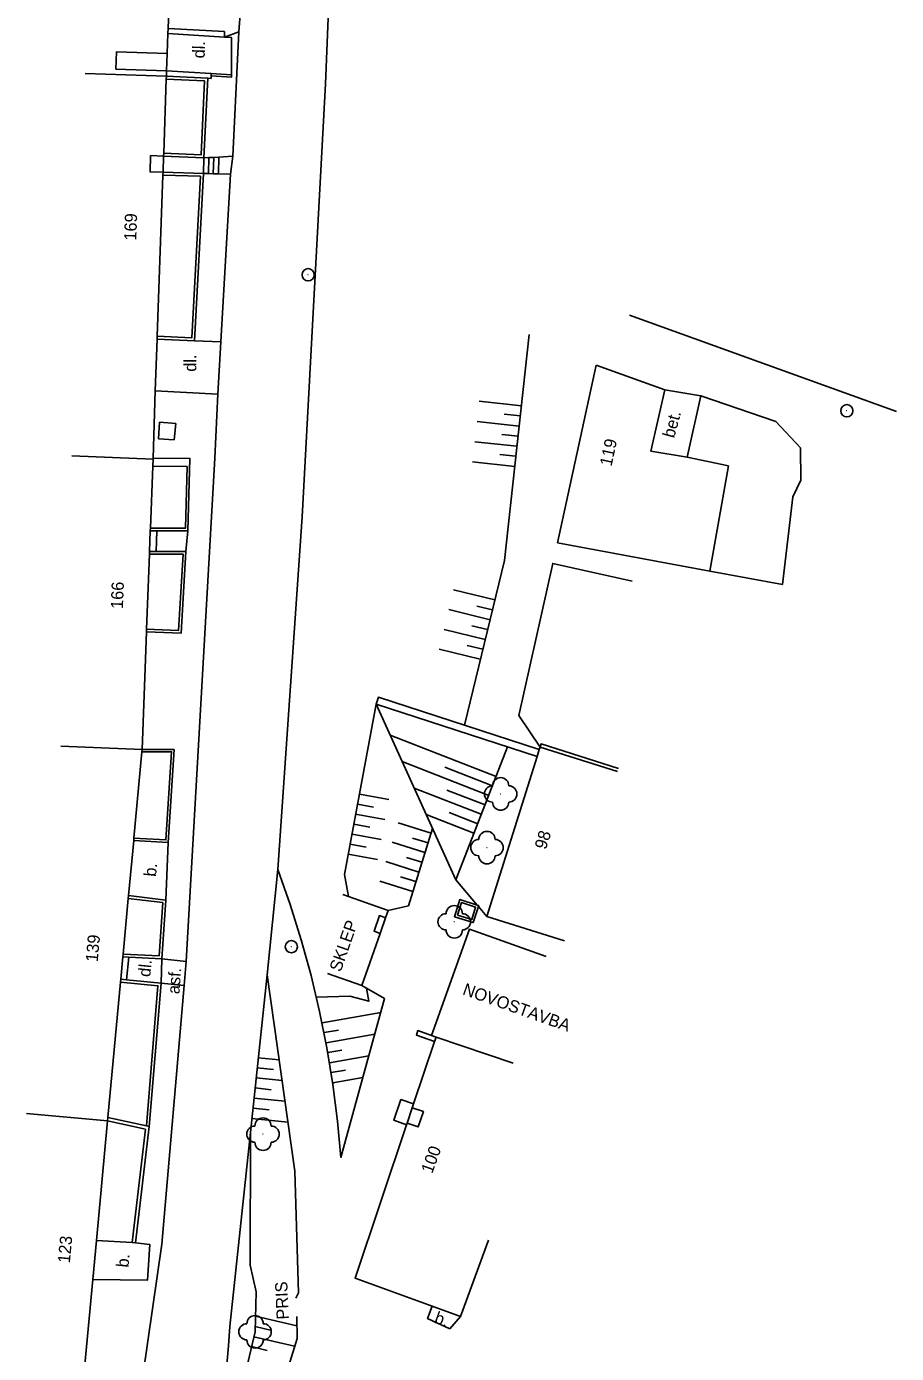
# Model space of a CAD drawing. Extents: x -582162 to -561283, y -1187583 to -1183539.
# Drawn here: x -571349.5 to -571296.1, y -1184989.4 to -1184907.8 of the extents above; entities that cross this region are included whole.
import ezdxf

# ---------------------------------------------------------------- set-up
doc = ezdxf.new("R2010")
doc.units = 0
for name, color, linetype in [('Vrstva 1', 7, 'Continuous'), ('Vrstva 10', 7, 'Continuous'), ('Vrstva 11', 7, 'Continuous'), ('Vrstva 12', 7, 'Continuous'), ('Vrstva 14', 7, 'Continuous'), ('Vrstva 4', 7, 'Continuous'), ('Vrstva 5', 7, 'Continuous'), ('Vrstva 6', 7, 'Continuous'), ('Vrstva 9', 7, 'Continuous')]:
    doc.layers.add(name, color=color, linetype=linetype)

# ---------------------------------------------------------------- blocks, each defined once
blk = doc.blocks.new('1.079')
at = {"layer": 'Vrstva 1'}
for radius in [0.75, 0.001]:
    blk.add_circle((0, -0.001), radius, dxfattribs=at)
blk = doc.blocks.new('3.130')
at = {"layer": 'Vrstva 1'}
blk.add_circle((0, 0), 0.001, dxfattribs=at)
for centre, start, end in [((0, 1), 0, 180), ((-1, 0), 90, 270), ((1, 0), 270, 90), ((0, -1), 180, 360)]:
    blk.add_arc(centre, 1, start, end, dxfattribs=at)

msp = doc.modelspace()

# ---------------------------------------------------------------- linework, layer by layer
at = {"layer": 'Vrstva 10'}
for points in [[(-571332.31, -1184869.17), (-571335.96, -1184901.1), (-571336.48, -1184908.14)], [(-571334.08, -1184959.63), (-571332.59, -1184937.95), (-571331.16, -1184911.33), (-571330.53, -1184895.66), (-571330.24, -1184892.9)], [(-571336.48, -1184908.14), (-571337.37, -1184908.46)], [(-571337.37, -1184908.46), (-571336.94, -1184908.48), (-571336.93, -1184910.78)], [(-571336.48, -1184908.14), (-571336.86, -1184915.79)], [(-571337.71, -1184915.84), (-571338.03, -1184915.86)], [(-571337.73, -1184916.87), (-571337.71, -1184915.84)], [(-571336.86, -1184915.79), (-571337.71, -1184915.84)], [(-571336.86, -1184915.79), (-571337, -1184916.88)], [(-571338.63, -1184915.89), (-571338.66, -1184916.85)], [(-571338.33, -1184915.87), (-571338.63, -1184915.89)], [(-571338.36, -1184916.85), (-571338.33, -1184915.87)], [(-571338.03, -1184915.86), (-571338.33, -1184915.87)], [(-571338.06, -1184916.86), (-571338.03, -1184915.86)], [(-571338.66, -1184916.85), (-571338.36, -1184916.85)], [(-571338.36, -1184916.85), (-571338.06, -1184916.86)], [(-571338.06, -1184916.86), (-571337.73, -1184916.87)], [(-571337.73, -1184916.87), (-571337, -1184916.88)], [(-571337, -1184916.88), (-571337.6, -1184927.19)], [(-571337.6, -1184927.19), (-571339.21, -1184927.14)], [(-571337.6, -1184927.19), (-571337.77, -1184930.41)], [(-571337.77, -1184930.41), (-571341.62, -1184930.21)], [(-571337.77, -1184930.41), (-571337.97, -1184934.35), (-571339.73, -1184965.27)], [(-571308.09, -1184930.51), (-571310.32, -1184930.14)], [(-571308.94, -1184934.29), (-571308.09, -1184930.51)], [(-571341.42, -1184933.16), (-571341.36, -1184932.14)], [(-571341.36, -1184932.14), (-571340.35, -1184932.21)], [(-571340.35, -1184932.21), (-571340.45, -1184933.22)], [(-571340.45, -1184933.22), (-571341.42, -1184933.16)], [(-571341.52, -1184938.8), (-571341.57, -1184940.08)], [(-571339.61, -1184938.82), (-571339.74, -1184940.09)], [(-571318.03, -1184952.25), (-571327.91, -1184949.04), (-571328.05, -1184949.47)], [(-571318.16, -1184952.68), (-571328.05, -1184949.47)], [(-571328.05, -1184949.47), (-571323.16, -1184960.25), (-571321.84, -1184961.81)], [(-571313.15, -1184953.41), (-571317.92, -1184951.91), (-571317.98, -1184952.1)], [(-571340.83, -1184957.97), (-571340.97, -1184961.5)], [(-571334.75, -1184966.09), (-571334.08, -1184959.63)], [(-571334.08, -1184959.63), (-571333.33, -1184961.78), (-571332.65, -1184963.95), (-571332.04, -1184966.14), (-571331.52, -1184968.36), (-571331.07, -1184970.59), (-571330.71, -1184972.84), (-571330.42, -1184975.09), (-571330.21, -1184977.32), (-571327.53, -1184967.56), (-571328.92, -1184966.75)], [(-571321.77, -1184961.9), (-571322.08, -1184962.89), (-571323.23, -1184962.53), (-571322.91, -1184961.47), (-571321.84, -1184961.81)], [(-571323.05, -1184962.43), (-571322.81, -1184961.66), (-571321.94, -1184961.94), (-571322.18, -1184962.7), (-571323.05, -1184962.43)], [(-571321.84, -1184961.81), (-571321.75, -1184961.84), (-571321.77, -1184961.9)], [(-571321.84, -1184961.81), (-571321.77, -1184961.9)], [(-571321.77, -1184961.9), (-571321.25, -1184962.51)], [(-571343.25, -1184965.02), (-571343.38, -1184966.4)], [(-571341.21, -1184965.12), (-571341.26, -1184966.61)], [(-571339.73, -1184965.27), (-571341.21, -1184965.12)], [(-571339.73, -1184965.27), (-571339.84, -1184966.76)], [(-571338.89, -1185000), (-571338.44, -1184998.07), (-571337.99, -1184995.8), (-571337.62, -1184993.52), (-571337.33, -1184991.22), (-571337.12, -1184988.91), (-571337.04, -1184987.72), (-571335.77, -1184975.78), (-571334.75, -1184966.09)], [(-571332.82, -1184985.64), (-571333.05, -1184978.17), (-571334.75, -1184966.09)], [(-571339.84, -1184966.76), (-571341.22, -1184982.66), (-571342.67, -1184992.73), (-571342.71, -1184993.13), (-571342.94, -1184995.04), (-571343.25, -1184996.93), (-571343.64, -1184998.81), (-571343.94, -1185000)], [(-571341.26, -1184966.61), (-571339.84, -1184966.76)], [(-571326.18, -1184975.31), (-571326.97, -1184975.04), (-571326.53, -1184973.77), (-571325.75, -1184974.03)], [(-571342.83, -1184982.58), (-571341.96, -1184982.67), (-571342.09, -1184984.86), (-571345.46, -1184984.82)], [(-571345.24, -1184982.43), (-571343.05, -1184982.56)], [(-571322.86, -1184987.1), (-571323.53, -1184987.85), (-571324.89, -1184987.23), (-571324.61, -1184986.46)], [(-571334.01, -1184992.04), (-571332.91, -1184988.45), (-571332.93, -1184987.1)]]:
    msp.add_lwpolyline(points, dxfattribs=at)
at = {"layer": 'Vrstva 12'}
for points in [[(-571321.71, -1184930.84), (-571319.12, -1184931.13)], [(-571321.85, -1184932.08), (-571319.26, -1184932.37)], [(-571320.18, -1184931.64), (-571319.19, -1184931.75)], [(-571320.32, -1184932.88), (-571319.33, -1184932.99)], [(-571321.99, -1184933.33), (-571319.4, -1184933.61)], [(-571322.12, -1184934.57), (-571319.53, -1184934.85)], [(-571320.45, -1184934.12), (-571319.46, -1184934.23)], [(-571323.29, -1184942.44), (-571320.76, -1184943.05)], [(-571321.87, -1184943.43), (-571320.91, -1184943.66)], [(-571323.58, -1184943.65), (-571321.05, -1184944.27)], [(-571323.88, -1184944.87), (-571321.35, -1184945.48)], [(-571322.17, -1184944.64), (-571321.2, -1184944.88)], [(-571322.46, -1184945.86), (-571321.5, -1184946.09)], [(-571324.18, -1184946.08), (-571321.65, -1184946.7)], [(-571327.19, -1184951.36), (-571320.68, -1184953.9)], [(-571326.45, -1184952.99), (-571321.13, -1184955.07)], [(-571323.83, -1184953.34), (-571320.91, -1184954.48)], [(-571327.28, -1184955.33), (-571329.08, -1184955)], [(-571325.71, -1184954.62), (-571321.59, -1184956.23)], [(-571323.7, -1184954.74), (-571321.36, -1184955.65)], [(-571328.21, -1184955.8), (-571329.19, -1184955.61)], [(-571327.51, -1184956.56), (-571329.31, -1184956.23)], [(-571324.97, -1184956.25), (-571322.04, -1184957.39)], [(-571323.56, -1184956.13), (-571321.81, -1184956.81)], [(-571328.44, -1184957.02), (-571329.42, -1184956.84)], [(-571326.7, -1184956.76), (-571324.67, -1184957.39)], [(-571328.67, -1184958.25), (-571329.65, -1184958.07)], [(-571327.74, -1184957.79), (-571329.53, -1184957.46)], [(-571327.07, -1184957.95), (-571325.05, -1184958.59)], [(-571325.81, -1184957.69), (-571324.86, -1184957.99)], [(-571327.97, -1184959.02), (-571329.76, -1184958.69)], [(-571326.18, -1184958.88), (-571325.24, -1184959.18)], [(-571327.45, -1184959.14), (-571325.42, -1184959.78)], [(-571327.82, -1184960.34), (-571325.8, -1184960.97)], [(-571326.56, -1184960.08), (-571325.61, -1184960.37)], [(-571327.76, -1184968.42), (-571331.37, -1184969.04)], [(-571330.36, -1184969.5), (-571331.25, -1184969.65)], [(-571328.13, -1184969.75), (-571331.13, -1184970.27)], [(-571334.01, -1184971.32), (-571335.29, -1184971.19)], [(-571330.15, -1184970.73), (-571331.02, -1184970.88)], [(-571328.5, -1184971.08), (-571330.91, -1184971.5)], [(-571334.36, -1184971.91), (-571335.35, -1184971.81)], [(-571329.94, -1184971.96), (-571330.81, -1184972.11)], [(-571333.83, -1184972.6), (-571335.42, -1184972.43)], [(-571328.86, -1184972.41), (-571330.72, -1184972.73)], [(-571333.65, -1184973.87), (-571335.55, -1184973.67)], [(-571334.49, -1184973.16), (-571335.48, -1184973.05)], [(-571334.62, -1184974.4), (-571335.61, -1184974.3)], [(-571333.47, -1184975.15), (-571335.68, -1184974.92)], [(-571332.93, -1184987.68), (-571335.46, -1184987.08)], [(-571333.06, -1184988.93), (-571335.56, -1184988.34)], [(-571334.45, -1184987.96), (-571335.48, -1184987.72)], [(-571334.74, -1184989.18), (-571335.71, -1184988.95)]]:
    msp.add_lwpolyline(points, dxfattribs=at)
at = {"layer": 'Vrstva 4'}
for points in [[(-571340.61, -1184901.83), (-571340.83, -1184907.93)], [(-571340.84, -1184908.24), (-571340.89, -1184909.47)], [(-571340.83, -1184907.93), (-571340.84, -1184908.24)], [(-571340.93, -1184910.54), (-571344.04, -1184910.43), (-571344, -1184909.36), (-571340.89, -1184909.47)], [(-571340.89, -1184909.47), (-571340.93, -1184910.54)], [(-571345.93, -1184910.7), (-571340.94, -1184910.87)], [(-571340.94, -1184910.87), (-571340.95, -1184911.05)], [(-571340.93, -1184910.54), (-571340.94, -1184910.87)], [(-571340.95, -1184911.05), (-571341.1, -1184915.6)], [(-571341.11, -1184915.78), (-571341.91, -1184915.75), (-571341.94, -1184916.75), (-571341.14, -1184916.77)], [(-571341.11, -1184915.78), (-571341.14, -1184916.77)], [(-571341.1, -1184915.6), (-571341.11, -1184915.78)], [(-571341.15, -1184916.95), (-571341.5, -1184926.85)], [(-571341.14, -1184916.77), (-571341.15, -1184916.95)], [(-571341.51, -1184927.03), (-571341.62, -1184930.21)], [(-571341.5, -1184926.85), (-571341.51, -1184927.03)], [(-571316.9, -1184939.55), (-571314.53, -1184928.63)], [(-571314.53, -1184928.63), (-571310.32, -1184930.14)], [(-571341.62, -1184930.21), (-571341.76, -1184934.34)], [(-571311.17, -1184933.92), (-571310.32, -1184930.14)], [(-571346.75, -1184934.21), (-571341.76, -1184934.4)], [(-571341.76, -1184934.4), (-571341.78, -1184934.84)], [(-571341.76, -1184934.34), (-571341.76, -1184934.4)], [(-571311.17, -1184933.92), (-571308.94, -1184934.29)], [(-571306.4, -1184934.82), (-571308.94, -1184934.29)], [(-571341.78, -1184934.84), (-571341.92, -1184938.64)], [(-571307.55, -1184941.29), (-571306.4, -1184934.82)], [(-571341.92, -1184938.64), (-571341.93, -1184938.8)], [(-571341.93, -1184938.8), (-571341.97, -1184940.08)], [(-571341.98, -1184940.24), (-571342.15, -1184944.85)], [(-571341.97, -1184940.08), (-571341.98, -1184940.24)], [(-571342.16, -1184945.01), (-571342.43, -1184952.24)], [(-571342.15, -1184944.85), (-571342.16, -1184945.01)], [(-571347.43, -1184952.05), (-571342.43, -1184952.24)], [(-571342.44, -1184952.39), (-571342.93, -1184957.69)], [(-571342.43, -1184952.24), (-571342.44, -1184952.39)], [(-571318.16, -1184952.68), (-571318.03, -1184952.25)], [(-571318.03, -1184952.25), (-571317.98, -1184952.1)], [(-571317.98, -1184952.1), (-571313.21, -1184953.6)], [(-571321.25, -1184962.51), (-571318.16, -1184952.68)], [(-571342.94, -1184957.84), (-571343.26, -1184961.23)], [(-571342.93, -1184957.69), (-571342.94, -1184957.84)], [(-571343.28, -1184961.41), (-571343.59, -1184964.82)], [(-571343.26, -1184961.23), (-571343.28, -1184961.41)], [(-571330.1, -1184961.16), (-571327.31, -1184962.14), (-571327.47, -1184962.59)], [(-571327.47, -1184962.59), (-571327.84, -1184962.46), (-571328.18, -1184963.42), (-571327.8, -1184963.55)], [(-571327.47, -1184962.59), (-571327.8, -1184963.55)], [(-571316.48, -1184964.01), (-571321.25, -1184962.51)], [(-571327.8, -1184963.55), (-571328.92, -1184966.75)], [(-571324.64, -1184969.83), (-571322.32, -1184963.3), (-571317.6, -1184964.97)], [(-571343.61, -1184965), (-571343.74, -1184966.37)], [(-571343.59, -1184964.82), (-571343.61, -1184965)], [(-571343.74, -1184966.37), (-571343.76, -1184966.55)], [(-571328.92, -1184966.75), (-571331.04, -1184966.01)], [(-571343.76, -1184966.55), (-571344.53, -1184974.86)], [(-571325.75, -1184974.03), (-571324.46, -1184970.19)], [(-571324.37, -1184969.93), (-571324.64, -1184969.83)], [(-571324.46, -1184970.19), (-571324.37, -1184969.93)], [(-571319.63, -1184971.52), (-571324.37, -1184969.93)], [(-571326.15, -1184975.22), (-571325.83, -1184974.27)], [(-571326.15, -1184975.22), (-571325.46, -1184975.45), (-571325.14, -1184974.5), (-571325.83, -1184974.27)], [(-571325.83, -1184974.27), (-571325.75, -1184974.03)], [(-571349.53, -1184974.62), (-571344.55, -1184975.08)], [(-571344.55, -1184975.08), (-571345.24, -1184982.43)], [(-571344.53, -1184974.86), (-571344.55, -1184975.08)], [(-571324.61, -1184986.46), (-571329.34, -1184984.74), (-571326.18, -1184975.31)], [(-571326.18, -1184975.31), (-571326.15, -1184975.22)], [(-571345.24, -1184982.43), (-571345.46, -1184984.82)], [(-571321.14, -1184982.4), (-571322.86, -1184987.1)], [(-571345.46, -1184984.82), (-571346.13, -1184992.02)], [(-571322.86, -1184987.1), (-571324.61, -1184986.46)]]:
    msp.add_lwpolyline(points, dxfattribs=at)
at = {"layer": 'Vrstva 5'}
msp.add_lwpolyline([(-571316.9, -1184939.55), (-571307.55, -1184941.29)], dxfattribs=at)
at = {"layer": 'Vrstva 9'}
for points in [[(-571337.37, -1184908.46), (-571340.84, -1184908.24)], [(-571340.83, -1184907.93), (-571337.37, -1184908.13), (-571337.37, -1184908.46)], [(-571338.4, -1184910.99), (-571340.94, -1184910.87)], [(-571338.18, -1184910.7), (-571340.93, -1184910.54)], [(-571338.19, -1184910.85), (-571338.19, -1184911), (-571338.4, -1184910.99)], [(-571338.18, -1184910.7), (-571338.19, -1184910.85)], [(-571336.93, -1184910.78), (-571336.94, -1184910.93), (-571338.19, -1184910.85)], [(-571338.18, -1184910.7), (-571336.93, -1184910.78)], [(-571341.1, -1184915.6), (-571338.8, -1184915.7), (-571338.59, -1184911.16), (-571340.95, -1184911.05)], [(-571338.63, -1184915.89), (-571338.4, -1184910.99)], [(-571341.11, -1184915.78), (-571338.63, -1184915.89)], [(-571341.5, -1184926.85), (-571339.38, -1184926.95), (-571338.85, -1184917.02), (-571341.15, -1184916.95)], [(-571338.66, -1184916.85), (-571341.14, -1184916.77)], [(-571339.21, -1184927.14), (-571338.66, -1184916.85)], [(-571312.48, -1184925.55), (-571296.08, -1184931.47)], [(-571341.51, -1184927.03), (-571339.21, -1184927.14)], [(-571318.64, -1184926.75), (-571320.17, -1184940.63), (-571322.63, -1184950.75)], [(-571303.49, -1184932.1), (-571308.09, -1184930.51)], [(-571301.97, -1184933.71), (-571303.49, -1184932.1)], [(-571301.95, -1184935.7), (-571301.97, -1184933.71)], [(-571339.61, -1184938.82), (-571339.49, -1184934.36), (-571341.76, -1184934.34)], [(-571341.92, -1184938.64), (-571339.77, -1184938.65), (-571339.67, -1184934.86), (-571341.78, -1184934.84)], [(-571301.95, -1184935.7), (-571302.44, -1184936.71)], [(-571303.08, -1184942.1), (-571302.44, -1184936.71)], [(-571341.93, -1184938.8), (-571341.52, -1184938.8)], [(-571341.52, -1184938.8), (-571339.61, -1184938.82)], [(-571342.16, -1184945.01), (-571340.03, -1184945.1), (-571339.74, -1184940.09)], [(-571341.98, -1184940.24), (-571339.91, -1184940.24), (-571340.19, -1184944.93), (-571342.15, -1184944.85)], [(-571341.57, -1184940.08), (-571341.97, -1184940.08)], [(-571339.74, -1184940.09), (-571341.57, -1184940.08)], [(-571319.29, -1184950.16), (-571317.2, -1184940.81), (-571312.32, -1184941.91)], [(-571307.55, -1184941.29), (-571303.08, -1184942.1)], [(-571329.74, -1184961.29), (-571330, -1184959.94), (-571328.05, -1184949.47)], [(-571319.29, -1184950.16), (-571317.98, -1184952.1)], [(-571342.44, -1184952.39), (-571340.62, -1184952.39), (-571340.97, -1184957.81), (-571342.93, -1184957.69)], [(-571342.43, -1184952.24), (-571340.46, -1184952.25), (-571340.83, -1184957.97)], [(-571323.16, -1184960.25), (-571319.97, -1184952.09)], [(-571327.31, -1184962.14), (-571326.07, -1184961.85), (-571324.58, -1184957.1)], [(-571340.83, -1184957.97), (-571342.94, -1184957.84)], [(-571343.28, -1184961.41), (-571341.16, -1184961.66), (-571341.38, -1184964.93), (-571343.59, -1184964.82)], [(-571343.26, -1184961.23), (-571340.97, -1184961.5)], [(-571340.97, -1184961.5), (-571341.21, -1184965.12)], [(-571343.25, -1184965.02), (-571343.61, -1184965)], [(-571341.21, -1184965.12), (-571343.25, -1184965.02)], [(-571343.74, -1184966.37), (-571343.38, -1184966.4)], [(-571343.38, -1184966.4), (-571341.26, -1184966.61)], [(-571343.76, -1184966.55), (-571341.46, -1184966.77), (-571342.16, -1184975.38)], [(-571341.26, -1184966.61), (-571341.99, -1184975.42)], [(-571331.72, -1184967.47), (-571329.67, -1184967.42), (-571328.49, -1184967.72), (-571328.65, -1184966.91)], [(-571324.46, -1184970.19), (-571325.58, -1184969.8), (-571325.49, -1184969.53), (-571324.64, -1184969.83)], [(-571343.05, -1184982.56), (-571342.23, -1184975.59), (-571344.55, -1184975.08)], [(-571342.16, -1184975.38), (-571344.53, -1184974.86)], [(-571341.99, -1184975.42), (-571342.16, -1184975.38)], [(-571341.99, -1184975.42), (-571342.83, -1184982.58)], [(-571338.41, -1185000), (-571338.04, -1184998.87), (-571335.49, -1184988.04), (-571335.42, -1184985.58), (-571335.78, -1184983.95), (-571335.77, -1184975.78)], [(-571342.83, -1184982.58), (-571343.05, -1184982.56)], [(-571332.98, -1184985.97), (-571332.82, -1184985.64)]]:
    msp.add_lwpolyline(points, dxfattribs=at)

# ---------------------------------------------------------------- block references
at = {"layer": 'Vrstva 1', "xscale": 0.5, "yscale": 0.5, "rotation": 90}
for p in [(-571332.23, -1184923.07), (-571299.13, -1184931.43), (-571333.26, -1184964.37)]:
    msp.add_blockref('1.079', p, dxfattribs=at)
at = {"layer": 'Vrstva 11', "xscale": 0.5, "yscale": 0.5}
for p in [(-571320.4, -1184954.98), (-571321.24, -1184958.28), (-571323.25, -1184962.84), (-571335, -1184975.89), (-571335.49, -1184988.04)]:
    msp.add_blockref('3.130', p, dxfattribs=at)

# ---------------------------------------------------------------- texts
at = {"layer": 'Vrstva 14'}
for s, rotation, p in [('dl.', 88.01, (-571338.59, -1184909.78)), ('dl.', 90, (-571339.1, -1184929.03)), ('bet.', 74.896, (-571309.74, -1184933.15)), ('b.', 84.669, (-571341.58, -1184960.09)), ('SKLEP', 70.702, (-571330.23, -1184965.96)), ('dl.', 84.669, (-571341.93, -1184966.25)), ('asf.', 85.74, (-571340.14, -1184967.3)), ('NOVOSTAVBA', 340.436, (-571322.79, -1184967.29)), ('b.', 84.69, (-571343.27, -1184984.11)), ('PRIS', 92.58, (-571333.41, -1184987.27)), ('b.', 339.954, (-571324.53, -1184987.47))]:
    msp.add_text(s, height=0.75, rotation=rotation, dxfattribs=at).set_placement(p)
at = {"layer": 'Vrstva 6'}
for s, rotation, p in [('169', 88.004, (-571342.79, -1184920.98)), ('119', 77.741, (-571313.59, -1184934.88)), ('166', 87.823, (-571343.61, -1184943.62)), ('98', 72.542, (-571317.62, -1184958.44)), ('139', 84.702, (-571345.16, -1184965.33)), ('100', 69.955, (-571324.61, -1184978.36)), ('123', 84.69, (-571346.87, -1184983.84))]:
    msp.add_text(s, height=0.75, rotation=rotation, dxfattribs=at).set_placement(p)

doc.saveas('drawing.dxf')
